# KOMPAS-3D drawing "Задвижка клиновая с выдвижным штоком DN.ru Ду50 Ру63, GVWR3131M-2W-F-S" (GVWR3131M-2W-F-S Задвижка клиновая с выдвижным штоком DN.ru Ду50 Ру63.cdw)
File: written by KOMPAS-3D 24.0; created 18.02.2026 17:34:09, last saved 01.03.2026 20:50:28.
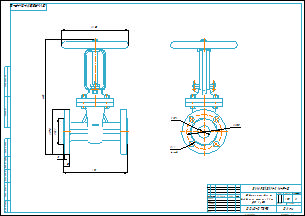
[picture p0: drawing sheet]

Document properties: art: D040-07393; Автор: R2D2; Форматы листов документа: A2; Полное имя файла: GVWR3131M-2W-F-S Задвижка клиновая с выдвижным штоком DN.ru Ду50 Ру63.m3d; Масса: 25.5; Наименование: Задвижка клиновая с выдвижным штоком DN.ru Ду50 Ру63; Количество листов документа: 1; Примечание: D040-07393

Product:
- Part/product: Задвижка клиновая с выдвижным штоком DN.ru Ду50 Ру63  | designation GVWR3131M-2W-F-S
    Масса: 25.5
    Раздел спецификации: Прочие изделия
    Примечание: D040-07393
    additional columns: D040-07393

Views: Вид 1, Спереди
Referenced files in E:\Работа\Зайцев\GVWR3131M-2W-F-S Задвижка клиновая с выдвижным штоком DN.ru Ду50-200 Ру63\DN50\: GVWR3131M-2W-F-S Задвижка клиновая с выдвижным штоком DN.ru Ду50 Ру63.m3d
Referenced files in E:\Работа\Зайцев\Для компаса\: чертеж DN.ru.cdt
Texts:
  GVWR3131M-2W-F-S
  чертеж DN.ru.cdt
  Задвижка клиновая с
  выдвижным штоком DN.ru
  Ду50 Ру63
  Задвижка клиновая с выдвижным штоком DN.ru Ду50 Ру63
  GVWR3131M-2W-F-S Задвижка клиновая с выдвижным штоком DN.ru Ду50 Ру63
Dimensions and other numbers on the sheet: 0; 3; 2; 4; 450; 250; 260; 26; 175; 102; 1:2; 1; 25,5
